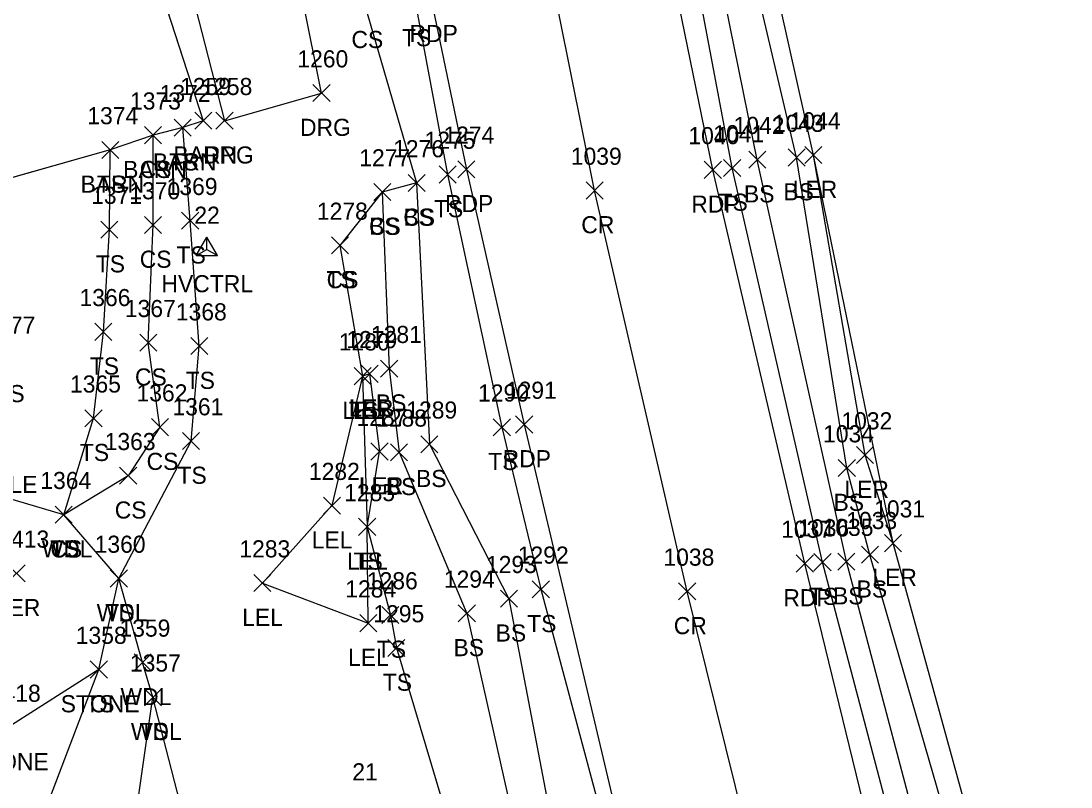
# Model space of a CAD drawing. Extents: x 1512665 to 1513714, y 110636 to 112816.
# Drawn here: x 1513164.9 to 1513287.6, y 110818.8 to 110908.3 of the extents above; entities that cross this region are included whole.
import ezdxf

# ---------------------------------------------------------------- set-up
doc = ezdxf.new("R2010")
doc.units = 0
for name, color, linetype in [('C_A', 7, 'Continuous'), ('C_I', 7, 'Continuous'), ('CPSM', 7, 'Continuous'), ('L_A', 7, 'Continuous'), ('L_C', 7, 'Continuous'), ('L_I', 7, 'Continuous'), ('L_TIC', 7, 'Continuous'), ('LARO', 7, 'Continuous'), ('LASF', 7, 'Continuous'), ('LAWA', 7, 'Continuous'), ('LBC', 7, 'Continuous'), ('LELB', 7, 'Continuous'), ('Level 13', 7, 'Continuous'), ('LSOGP', 7, 'Continuous'), ('P_A', 7, 'Continuous'), ('P_I', 7, 'Continuous'), ('P_TIC', 7, 'Continuous'), ('PET', 7, 'Continuous'), ('PRC', 7, 'Continuous'), ('R_A', 7, 'Continuous'), ('R_I', 7, 'Continuous'), ('R_TIC', 7, 'Continuous'), ('RDG', 7, 'Continuous')]:
    doc.layers.add(name, color=color, linetype=linetype)

msp = doc.modelspace()

# ---------------------------------------------------------------- linework, layer by layer
at = {"layer": 'CPSM'}
for p, q in [((1513185.39, 110880.84), (1513186.64, 110883)), ((1513187.89, 110880.84), (1513186.64, 110883)), ((1513186.64, 110881.56), (1513186.64, 110883)), ((1513185.39, 110880.84), (1513186.64, 110881.56)), ((1513186.64, 110881.56), (1513186.64, 110881.56)), ((1513186.64, 110881.56), (1513187.89, 110880.84)), ((1513185.39, 110880.84), (1513187.89, 110880.84))]:
    msp.add_line(p, q, dxfattribs=at)
at = {"layer": 'L_TIC'}
for points in [[(1513185.21, 110895.6), (1513187.21, 110897.6)], [(1513187.21, 110895.6), (1513185.21, 110897.6)], [(1513182.81, 110894.79), (1513184.81, 110896.79)], [(1513184.81, 110894.79), (1513182.81, 110896.79)], [(1513182.81, 110894.79), (1513184.81, 110896.79)], [(1513184.81, 110894.79), (1513182.81, 110896.79)], [(1513179.34, 110893.91), (1513181.34, 110895.91)], [(1513181.34, 110893.91), (1513179.34, 110895.91)], [(1513179.34, 110893.91), (1513181.34, 110895.91)], [(1513181.34, 110893.91), (1513179.34, 110895.91)], [(1513174.35, 110892.19), (1513176.35, 110894.19)], [(1513176.35, 110892.19), (1513174.35, 110894.19)], [(1513174.35, 110892.19), (1513176.35, 110894.19)], [(1513176.35, 110892.19), (1513174.35, 110894.19)], [(1513256.52, 110891.59), (1513258.52, 110893.59)], [(1513258.52, 110891.59), (1513256.52, 110893.59)], [(1513249.96, 110891.05), (1513251.96, 110893.05)], [(1513251.96, 110891.05), (1513249.96, 110893.05)], [(1513254.56, 110891.3), (1513256.56, 110893.3)], [(1513256.56, 110891.3), (1513254.56, 110893.3)], [(1513213.77, 110889.32), (1513215.77, 110891.32)], [(1513215.77, 110889.32), (1513213.77, 110891.32)], [(1513247.03, 110890.08), (1513249.03, 110892.08)], [(1513249.03, 110890.08), (1513247.03, 110892.08)], [(1513210.15, 110888.33), (1513212.15, 110890.33)], [(1513212.15, 110888.33), (1513210.15, 110890.33)], [(1513210.15, 110888.33), (1513212.15, 110890.33)], [(1513212.15, 110888.33), (1513210.15, 110890.33)], [(1513206.14, 110887.27), (1513208.14, 110889.27)], [(1513208.14, 110887.27), (1513206.14, 110889.27)], [(1513206.14, 110887.27), (1513208.14, 110889.27)], [(1513208.14, 110887.27), (1513206.14, 110889.27)], [(1513179.35, 110883.42), (1513181.35, 110885.42)], [(1513181.35, 110883.42), (1513179.35, 110885.42)], [(1513183.68, 110883.92), (1513185.68, 110885.92)], [(1513185.68, 110883.92), (1513183.68, 110885.92)], [(1513174.24, 110882.88), (1513176.24, 110884.88)], [(1513176.24, 110882.88), (1513174.24, 110884.88)], [(1513201.19, 110881.03), (1513203.19, 110883.03)], [(1513203.19, 110881.03), (1513201.19, 110883.03)], [(1513201.19, 110881.03), (1513203.19, 110883.03)], [(1513203.19, 110881.03), (1513201.19, 110883.03)], [(1513173.54, 110870.94), (1513175.54, 110872.94)], [(1513175.54, 110870.94), (1513173.54, 110872.94)], [(1513178.79, 110869.66), (1513180.79, 110871.66)], [(1513180.79, 110869.66), (1513178.79, 110871.66)], [(1513184.75, 110869.27), (1513186.75, 110871.27)], [(1513186.75, 110869.27), (1513184.75, 110871.27)], [(1513204.65, 110866.03), (1513206.65, 110868.03)], [(1513206.65, 110866.03), (1513204.65, 110868.03)], [(1513204.65, 110866.03), (1513206.65, 110868.03)], [(1513206.65, 110866.03), (1513204.65, 110868.03)], [(1513206.94, 110866.63), (1513208.94, 110868.63)], [(1513208.94, 110866.63), (1513206.94, 110868.63)], [(1513203.83, 110865.76), (1513205.83, 110867.76)], [(1513205.83, 110865.76), (1513203.83, 110867.76)], [(1513203.83, 110865.76), (1513205.83, 110867.76)], [(1513205.83, 110865.76), (1513203.83, 110867.76)], [(1513172.38, 110860.84), (1513174.38, 110862.84)], [(1513174.38, 110860.84), (1513172.38, 110862.84)], [(1513180.15, 110859.8), (1513182.15, 110861.8)], [(1513182.15, 110859.8), (1513180.15, 110861.8)], [(1513180.15, 110859.8), (1513182.15, 110861.8)], [(1513182.15, 110859.8), (1513180.15, 110861.8)], [(1513220.11, 110859.79), (1513222.11, 110861.79)], [(1513222.11, 110859.79), (1513220.11, 110861.79)], [(1513183.79, 110858.18), (1513185.79, 110860.18)], [(1513185.79, 110858.18), (1513183.79, 110860.18)], [(1513211.64, 110857.8), (1513213.64, 110859.8)], [(1513213.64, 110857.8), (1513211.64, 110859.8)], [(1513205.81, 110856.95), (1513207.81, 110858.95)], [(1513207.81, 110856.95), (1513205.81, 110858.95)], [(1513205.81, 110856.95), (1513207.81, 110858.95)], [(1513207.81, 110856.95), (1513205.81, 110858.95)], [(1513208.1, 110856.86), (1513210.1, 110858.86)], [(1513210.1, 110856.86), (1513208.1, 110858.86)], [(1513262.56, 110856.54), (1513264.56, 110858.54)], [(1513264.56, 110856.54), (1513262.56, 110858.54)], [(1513260.43, 110855.02), (1513262.43, 110857.02)], [(1513262.43, 110855.02), (1513260.43, 110857.02)], [(1513176.43, 110854.12), (1513178.43, 110856.12)], [(1513178.43, 110854.12), (1513176.43, 110856.12)], [(1513200.25, 110850.63), (1513202.25, 110852.63)], [(1513202.25, 110850.63), (1513200.25, 110852.63)], [(1513168.91, 110849.57), (1513170.91, 110851.57)], [(1513170.91, 110849.57), (1513168.91, 110851.57)], [(1513168.91, 110849.57), (1513170.91, 110851.57)], [(1513170.91, 110849.57), (1513168.91, 110851.57)], [(1513168.91, 110849.57), (1513170.91, 110851.57)], [(1513170.91, 110849.57), (1513168.91, 110851.57)], [(1513204.37, 110848.15), (1513206.37, 110850.15)], [(1513206.37, 110848.15), (1513204.37, 110850.15)], [(1513204.37, 110848.15), (1513206.37, 110850.15)], [(1513206.37, 110848.15), (1513204.37, 110850.15)], [(1513265.83, 110846.25), (1513267.83, 110848.25)], [(1513267.83, 110846.25), (1513265.83, 110848.25)], [(1513257.58, 110844.03), (1513259.58, 110846.03)], [(1513259.58, 110844.03), (1513257.58, 110846.03)], [(1513260.37, 110844.09), (1513262.37, 110846.09)], [(1513262.37, 110844.09), (1513260.37, 110846.09)], [(1513263.13, 110844.89), (1513265.13, 110846.89)], [(1513265.13, 110844.89), (1513263.13, 110846.89)], [(1513163.39, 110842.72), (1513165.39, 110844.72)], [(1513165.39, 110842.72), (1513163.39, 110844.72)], [(1513175.34, 110842.12), (1513177.34, 110844.12)], [(1513177.34, 110842.12), (1513175.34, 110844.12)], [(1513175.34, 110842.12), (1513177.34, 110844.12)], [(1513177.34, 110842.12), (1513175.34, 110844.12)], [(1513192.12, 110841.58), (1513194.12, 110843.58)], [(1513194.12, 110841.58), (1513192.12, 110843.58)], [(1513224.66, 110840.85), (1513226.66, 110842.85)], [(1513226.66, 110840.85), (1513224.66, 110842.85)], [(1513220.94, 110839.75), (1513222.94, 110841.75)], [(1513222.94, 110839.75), (1513220.94, 110841.75)], [(1513207.08, 110837.85), (1513209.08, 110839.85)], [(1513209.08, 110837.85), (1513207.08, 110839.85)], [(1513216.02, 110838.04), (1513218.02, 110840.04)], [(1513218.02, 110838.04), (1513216.02, 110840.04)], [(1513204.5, 110836.9), (1513206.5, 110838.9)], [(1513206.5, 110836.9), (1513204.5, 110838.9)], [(1513207.78, 110834), (1513209.78, 110836)], [(1513209.78, 110834), (1513207.78, 110836)], [(1513173.01, 110831.48), (1513175.01, 110833.48)], [(1513175.01, 110831.48), (1513173.01, 110833.48)], [(1513173.01, 110831.48), (1513175.01, 110833.48)], [(1513175.01, 110831.48), (1513173.01, 110833.48)], [(1513178.12, 110832.32), (1513180.12, 110834.32)], [(1513180.12, 110832.32), (1513178.12, 110834.32)], [(1513179.33, 110828.24), (1513181.33, 110830.24)], [(1513181.33, 110828.24), (1513179.33, 110830.24)], [(1513179.33, 110828.24), (1513181.33, 110830.24)], [(1513181.33, 110828.24), (1513179.33, 110830.24)]]:
    msp.add_lwpolyline(points, dxfattribs=at)
at = {"layer": 'LARO'}
for points in [[(1513287.62, 110771.43), (1513278.66, 110804.35), (1513266.83, 110847.25), (1513263.56, 110857.54), (1513257.52, 110892.59), (1513246.98, 110939.88), (1513240.55, 110972.35), (1513236.76, 111000.77), (1513232.04, 111040.6), (1513226.98, 111080.02), (1513225.56, 111103.19), (1513223, 111134)], [(1513205.65, 110867.03), (1513204.83, 110866.76), (1513201.25, 110851.63), (1513193.12, 110842.58), (1513205.5, 110837.9), (1513205.37, 110849.15), (1513206.81, 110857.95)], [(1513205.65, 110867.03), (1513206.81, 110857.95)]]:
    msp.add_lwpolyline(points, dxfattribs=at)
at = {"layer": 'LASF'}
msp.add_lwpolyline([(1513155.27, 110725.13), (1513152.55, 110754.36), (1513148, 110771.81), (1513152.25, 110792.5), (1513164.38, 110807.2), (1513174.01, 110832.48), (1513163.39, 110825.71), (1513157.64, 110817.68), (1513150.03, 110815.28), (1513143.72, 110818.88), (1513137.14, 110819.49), (1513132.38, 110806.57), (1513129.37, 110796.51), (1513123.12, 110784.14), (1513118.15, 110774.69), (1513122.72, 110764.73), (1513123.65, 110752.31), (1513122.83, 110742.42), (1513125.74, 110723.52), (1513127.35, 110710.17)], dxfattribs=at)
at = {"layer": 'LAWA'}
msp.add_lwpolyline([(1513197.25, 110742.91), (1513197.01, 110757.62), (1513193.44, 110768.94), (1513192.26, 110775.56), (1513188.92, 110789.13), (1513185.03, 110810.98), (1513180.33, 110829.24), (1513179.12, 110833.32), (1513176.34, 110843.12), (1513169.91, 110850.57), (1513155.8, 110854.74)], dxfattribs=at)
at = {"layer": 'LBC'}
msp.add_lwpolyline([(1513141.52, 110909.73), (1513161.13, 110914.73), (1513177.09, 110919.23), (1513179.12, 110918.46), (1513186.21, 110896.6), (1513183.81, 110895.79), (1513180.34, 110894.91), (1513175.35, 110893.19), (1513159.49, 110888.71), (1513147.82, 110885.55), (1513142.89, 110884.18), (1513140.56, 110883.67), (1513137.34, 110882.9), (1513136.07, 110882.64), (1513129.77, 110906.51)], dxfattribs=at)
at = {"layer": 'LELB'}
for points in [[(1513279.66, 110769.09), (1513269.36, 110804.1), (1513258.58, 110845.03), (1513248.03, 110891.08), (1513238.9, 110939.46), (1513233.67, 110971.28), (1513227.79, 110999.01), (1513223.28, 111039.29), (1513218.14, 111079.84), (1513215.66, 111101.58), (1513213.58, 111134.44)], [(1513281.07, 110769.49), (1513272.18, 110804.3), (1513261.37, 110845.09), (1513250.96, 110892.05), (1513241.33, 110939.47), (1513235.95, 110971.69), (1513230.75, 110998.96), (1513225.38, 111039.55), (1513220.72, 111079.68), (1513217.65, 111101.89), (1513215.41, 111134.66)], [(1513285.37, 110770.76), (1513275.94, 110804.91), (1513264.13, 110845.89), (1513261.43, 110856.02), (1513255.56, 110892.3), (1513244.37, 110939.84), (1513238.1, 110972.49), (1513234.78, 111000.27), (1513229.59, 111040.61), (1513225.06, 111080), (1513223.07, 111102.56), (1513220.29, 111134.39)], [(1513192.44, 110970.36), (1513199.85, 110941), (1513205.09, 110910.09), (1513211.15, 110889.33), (1513207.14, 110888.27), (1513202.19, 110882.03)], [(1513199.08, 110968.9), (1513204.16, 110941.9), (1513211.03, 110910.3), (1513214.77, 110890.32), (1513221.11, 110860.79), (1513225.66, 110841.85), (1513234.54, 110808.65), (1513239.21, 110788.36), (1513247.66, 110759.74)], [(1513174.01, 110832.48), (1513176.34, 110843.12), (1513184.79, 110859.18), (1513185.75, 110870.27), (1513184.68, 110884.92), (1513183.81, 110895.79)], [(1513181.15, 110860.8), (1513179.79, 110870.66), (1513180.35, 110884.42), (1513180.34, 110894.91)], [(1513169.91, 110850.57), (1513173.38, 110861.84), (1513174.54, 110871.94), (1513175.24, 110883.88), (1513175.35, 110893.19)], [(1513211.15, 110889.33), (1513212.64, 110858.8), (1513221.94, 110840.75), (1513228.33, 110807.28), (1513235.23, 110787.8), (1513241.76, 110757.2)], [(1513207.14, 110888.27), (1513207.94, 110867.63), (1513209.1, 110857.86), (1513217.02, 110839.04), (1513224.44, 110805.93), (1513230.78, 110786.87), (1513237.59, 110755.82)], [(1513202.19, 110882.03), (1513204.83, 110866.76), (1513205.37, 110849.15), (1513208.08, 110838.85), (1513208.78, 110835), (1513215.64, 110812.05), (1513218.31, 110804.11), (1513223.4, 110786.76), (1513231.77, 110753.79)], [(1513181.15, 110860.8), (1513177.43, 110855.12), (1513169.91, 110850.57)], [(1513174.02, 110768.97), (1513167.62, 110779.02), (1513172.94, 110795.28), (1513177.4, 110808.9), (1513180.33, 110829.24)]]:
    msp.add_lwpolyline(points, dxfattribs=at)
at = {"layer": 'Level 13'}
for p, q in [((1513179.11, 110918.45), (1513186.2, 110896.6)), ((1513186.2, 110896.6), (1513183.81, 110895.8)), ((1513180.34, 110894.92), (1513175.35, 110893.2)), ((1513183.81, 110895.8), (1513180.34, 110894.92)), ((1513175.35, 110893.2), (1513159.5, 110888.71))]:
    msp.add_line(p, q, dxfattribs=at)
at = {"layer": 'LSOGP'}
msp.add_lwpolyline([(1513155.27, 110725.13), (1513174.53, 110733.79), (1513179.3, 110737.27), (1513197.25, 110742.91), (1513212.66, 110748.89), (1513231.77, 110753.79), (1513237.59, 110755.82), (1513241.76, 110757.2), (1513249.29, 110760.25), (1513262.69, 110765.32), (1513276.33, 110768.1), (1513279.66, 110769.08), (1513281.07, 110769.49), (1513285.37, 110770.76), (1513287.62, 110771.44), (1513278.65, 110804.35), (1513266.83, 110847.25), (1513257.52, 110892.59), (1513246.98, 110939.88)], dxfattribs=at)
at = {"layer": 'P_TIC'}
for points in [[(1513215.97, 110889.92), (1513217.97, 110891.92)], [(1513217.97, 110889.92), (1513215.97, 110891.92)], [(1513244.76, 110889.86), (1513246.76, 110891.86)], [(1513246.76, 110889.86), (1513244.76, 110891.86)], [(1513230.95, 110887.45), (1513232.95, 110889.45)], [(1513232.95, 110887.45), (1513230.95, 110889.45)], [(1513222.71, 110860.11), (1513224.71, 110862.11)], [(1513224.71, 110860.11), (1513222.71, 110862.11)], [(1513255.52, 110843.87), (1513257.52, 110845.87)], [(1513257.52, 110843.87), (1513255.52, 110845.87)], [(1513241.77, 110840.61), (1513243.77, 110842.61)], [(1513243.77, 110840.61), (1513241.77, 110842.61)]]:
    msp.add_lwpolyline(points, dxfattribs=at)
at = {"layer": 'PET'}
for points in [[(1513276.33, 110768.1), (1513266.56, 110803.7), (1513256.52, 110844.87), (1513245.76, 110890.86), (1513235.93, 110938.82), (1513230.25, 110971.16), (1513225.99, 110998.82), (1513220.55, 111038.9), (1513215.66, 111079.61), (1513213.11, 111101.63), (1513210.3, 111134.17)], [(1513181.78, 111131.32), (1513183.34, 111114.05), (1513184.43, 111101.24), (1513188.03, 111069.41), (1513191.64, 111039.85), (1513195.64, 111010.58), (1513196.78, 111002.78), (1513199.52, 110982.68), (1513202.26, 110966.84), (1513206.8, 110942.1), (1513212.83, 110910.79), (1513216.97, 110890.92), (1513223.71, 110861.11), (1513236.04, 110809.07), (1513241.46, 110788.53), (1513249.29, 110760.24)]]:
    msp.add_lwpolyline(points, dxfattribs=at)
at = {"layer": 'PRC'}
msp.add_lwpolyline([(1513262.69, 110765.32), (1513252.95, 110800.58), (1513242.77, 110841.61), (1513231.95, 110888.45), (1513222.37, 110936.12), (1513216.37, 110968.76), (1513211.8, 110996.68), (1513206.03, 111035.98), (1513201.18, 111077.25), (1513198.65, 111101.07), (1513195.74, 111132.86)], dxfattribs=at)
at = {"layer": 'R_TIC'}
for points in [[(1513199.03, 110898.83), (1513201.03, 110900.83)], [(1513201.03, 110898.83), (1513199.03, 110900.83)], [(1513187.69, 110895.6), (1513189.69, 110897.6)], [(1513189.69, 110895.6), (1513187.69, 110897.6)]]:
    msp.add_lwpolyline(points, dxfattribs=at)
at = {"layer": 'RDG'}
msp.add_lwpolyline([(1513173.34, 110967.11), (1513172.43, 110957.22), (1513176.53, 110938.45), (1513182.22, 110921.82), (1513188.69, 110896.6), (1513200.03, 110899.83), (1513195.61, 110921.77), (1513191.1, 110941.68), (1513186.33, 110960.8), (1513187.14, 110969.63)], dxfattribs=at)

# ---------------------------------------------------------------- texts
at = {"layer": 'C_A'}
msp.add_text('HVCTRL', height=2, dxfattribs=at).set_placement((1513181.33, 110876.56))
at = {"layer": 'C_I'}
for s, p in [('22', (1513185.17, 110884.56)), ('21', (1513203.63, 110819.53))]:
    msp.add_text(s, height=2, dxfattribs=at).set_placement(p)
at = {"layer": 'L_A'}
for s, p in [('CS', (1513203.53, 110905.09)), ('TS', (1513209.44, 110905.3)), ('BARN', (1513182.73, 110891.6)), ('BARN', (1513180.32, 110890.79)), ('TS', (1513182.22, 110890.79)), ('BARN', (1513176.85, 110889.91)), ('CS', (1513178.78, 110889.91)), ('BARN', (1513171.87, 110888.19)), ('TS', (1513173.76, 110888.19)), ('BS', (1513249.4, 110887.05)), ('BS', (1513254.01, 110887.3)), ('LER', (1513255.1, 110887.59)), ('TS', (1513246.44, 110886.08)), ('CS', (1513209.59, 110884.33)), ('BS', (1513209.59, 110884.33)), ('TS', (1513213.18, 110885.32)), ('CS', (1513205.58, 110883.27)), ('BS', (1513205.58, 110883.27)), ('CS', (1513178.79, 110879.42)), ('TS', (1513183.09, 110879.92)), ('TS', (1513173.65, 110878.88)), ('TS', (1513200.6, 110877.03)), ('CS', (1513200.63, 110877.03)), ('TS', (1513172.95, 110866.94)), ('CS', (1513178.23, 110865.66)), ('TS', (1513184.16, 110865.27)), ('BS', (1513161.77, 110863.72)), ('BS', (1513206.38, 110862.63)), ('LEL', (1513202.47, 110861.76)), ('TS', (1513203.24, 110861.76)), ('LER', (1513203.23, 110862.03)), ('LEL', (1513203.28, 110862.03)), ('TS', (1513171.79, 110856.84)), ('CS', (1513179.59, 110855.8)), ('CS', (1513179.59, 110855.8)), ('TS', (1513219.52, 110855.79)), ('TS', (1513183.2, 110854.18)), ('BS', (1513211.08, 110853.8)), ('LER', (1513204.4, 110852.95)), ('LEL', (1513204.45, 110852.95)), ('BS', (1513207.54, 110852.86)), ('LER', (1513261.14, 110852.54)), ('CS', (1513175.87, 110850.12)), ('BS', (1513259.87, 110851.02)), ('LEL', (1513198.89, 110846.63)), ('WDL', (1513167.33, 110845.57)), ('TS', (1513168.32, 110845.57)), ('CS', (1513168.35, 110845.57)), ('LEL', (1513203.01, 110844.15)), ('TS', (1513203.78, 110844.15)), ('LER', (1513264.41, 110842.25)), ('TS', (1513256.99, 110840.03)), ('BS', (1513259.81, 110840.09)), ('BS', (1513262.57, 110840.89)), ('LER', (1513161.97, 110838.72)), ('WDL', (1513173.76, 110838.12)), ('TS', (1513174.75, 110838.12)), ('LEL', (1513190.76, 110837.58)), ('TS', (1513224.07, 110836.85)), ('BS', (1513220.38, 110835.75)), ('BS', (1513215.46, 110834.04)), ('LEL', (1513203.14, 110832.9)), ('TS', (1513206.49, 110833.85)), ('TS', (1513207.19, 110830)), ('WDL', (1513176.54, 110828.32)), ('STONE', (1513169.55, 110827.48)), ('TS', (1513172.42, 110827.48)), ('WDL', (1513177.75, 110824.24)), ('TS', (1513178.74, 110824.24)), ('STONE', (1513158.94, 110820.71))]:
    msp.add_text(s, height=2, dxfattribs=at).set_placement(p)
at = {"layer": 'L_C'}
msp.add_text('M.APPLE', height=2, dxfattribs=at).set_placement((1513155.24, 110853.1))
at = {"layer": 'L_I'}
for s, p in [('1259', (1513183.51, 110899.6)), ('1373', (1513177.65, 110897.91)), ('1373', (1513177.65, 110897.91)), ('1372', (1513181.12, 110898.79)), ('1372', (1513181.12, 110898.79)), ('1374', (1513172.66, 110896.19)), ('1374', (1513172.66, 110896.19)), ('1043', (1513252.79, 110895.3)), ('1044', (1513254.75, 110895.59)), ('1041', (1513245.82, 110894.08)), ('1042', (1513248.19, 110895.05)), ('1275', (1513212.08, 110893.32)), ('1276', (1513208.4, 110892.33)), ('1276', (1513208.4, 110892.33)), ('1277', (1513204.44, 110891.27)), ('1277', (1513204.44, 110891.27)), ('1369', (1513181.93, 110887.92)), ('1371', (1513173.11, 110886.88)), ('1370', (1513177.57, 110887.42)), ('1278', (1513199.49, 110885.03)), ('1278', (1513199.49, 110885.03)), ('1366', (1513171.75, 110874.94)), ('1367', (1513177.05, 110873.66)), ('1368', (1513183.01, 110873.27)), ('1377', (1513160.64, 110871.72)), ('1280', (1513202.05, 110869.76)), ('1280', (1513202.05, 110869.76)), ('1279', (1513202.94, 110870.03)), ('1279', (1513202.94, 110870.03)), ('1281', (1513205.81, 110870.63)), ('1365', (1513170.64, 110864.84)), ('1362', (1513178.41, 110863.8)), ('1362', (1513178.41, 110863.8)), ('1290', (1513218.33, 110863.79)), ('1361', (1513182.61, 110862.18)), ('1287', (1513204.12, 110860.95)), ('1287', (1513204.12, 110860.95)), ('1288', (1513206.41, 110860.86)), ('1289', (1513209.94, 110861.8)), ('1032', (1513260.79, 110860.54)), ('1034', (1513258.65, 110859.02)), ('1363', (1513174.69, 110858.12)), ('1364', (1513167.17, 110853.57)), ('1364', (1513167.17, 110853.57)), ('1364', (1513167.17, 110853.57)), ('1282', (1513198.56, 110854.63)), ('1285', (1513202.68, 110852.15)), ('1285', (1513202.68, 110852.15)), ('1031', (1513264.62, 110850.25)), ('1033', (1513261.36, 110848.89)), ('1036', (1513255.75, 110848.03)), ('1035', (1513258.59, 110848.09)), ('1413', (1513162.26, 110846.72)), ('1360', (1513173.52, 110846.12)), ('1360', (1513173.52, 110846.12)), ('1283', (1513190.43, 110845.58)), ('1293', (1513219.25, 110843.75)), ('1292', (1513222.97, 110844.85)), ('1286', (1513205.33, 110841.85)), ('1294', (1513214.33, 110842.04)), ('1284', (1513202.81, 110840.9)), ('1295', (1513206.09, 110838)), ('1359', (1513176.42, 110836.32)), ('1358', (1513171.31, 110835.48)), ('1358', (1513171.31, 110835.48)), ('1357', (1513177.64, 110832.24)), ('1357', (1513177.64, 110832.24)), ('1418', (1513161.27, 110828.71))]:
    msp.add_text(s, height=2, dxfattribs=at).set_placement(p)
at = {"layer": 'P_A'}
for s, p in [('RDP', (1513210.32, 110905.79)), ('RDP', (1513214.46, 110885.92)), ('RDP', (1513243.25, 110885.86)), ('CR', (1513230.39, 110883.45)), ('RDP', (1513221.2, 110856.11)), ('RDP', (1513254.01, 110839.87)), ('CR', (1513241.2, 110836.61))]:
    msp.add_text(s, height=2, dxfattribs=at).set_placement(p)
at = {"layer": 'P_I'}
for s, p in [('1274', (1513214.28, 110893.92)), ('1040', (1513242.91, 110893.86)), ('1039', (1513229.17, 110891.45)), ('1291', (1513221.58, 110864.11)), ('1037', (1513253.75, 110847.87)), ('1038', (1513239.99, 110844.61))]:
    msp.add_text(s, height=2, dxfattribs=at).set_placement(p)
at = {"layer": 'R_A'}
for p in [(1513197.52, 110894.83), (1513186.18, 110891.6)]:
    msp.add_text('DRG', height=2, dxfattribs=at).set_placement(p)
at = {"layer": 'R_I'}
for s, p in [('1260', (1513197.21, 110902.83)), ('1258', (1513186, 110899.6))]:
    msp.add_text(s, height=2, dxfattribs=at).set_placement(p)

doc.saveas('drawing.dxf')
